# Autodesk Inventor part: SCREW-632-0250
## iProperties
Created: 2007-08
Part Number: SCREW-632-0250
Document SubType Name: Modeling
Material: Stainless Steel
Density: 8.08 g/cm^3
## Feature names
1. Base1
